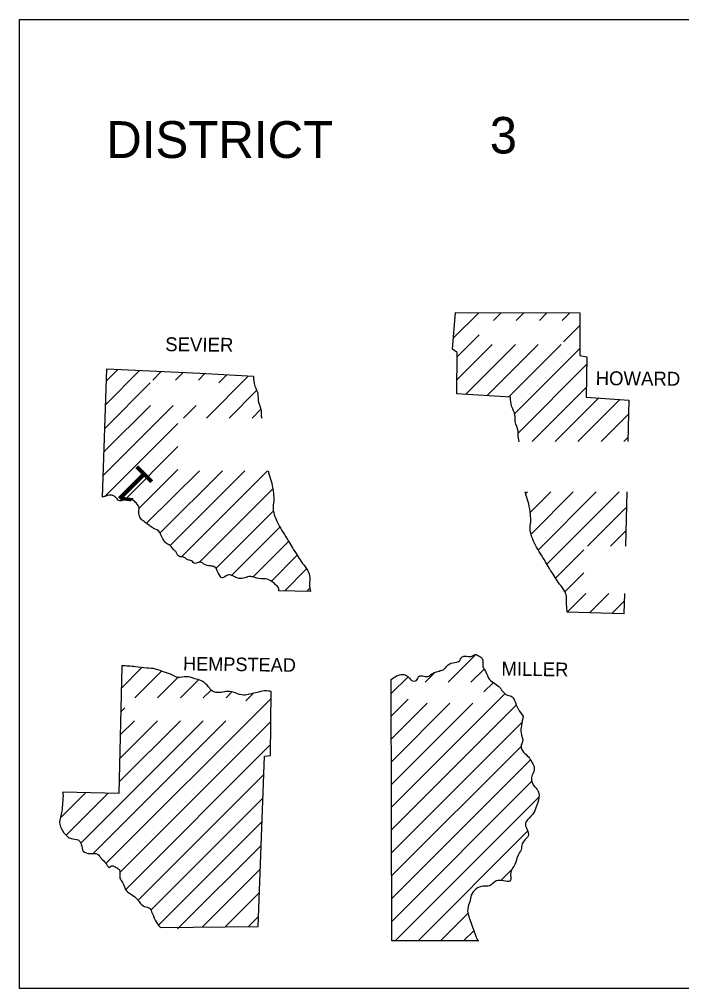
# Model space of a CAD drawing. Extents: x 23481 to 28196, y 1325020 to 1327623.
# Drawn here: x 27550.2 to 27755.3, y 1327036.8 to 1327336.8 of the extents above; entities that cross this region are included whole.
import ezdxf

# ---------------------------------------------------------------- set-up
doc = ezdxf.new("R2010")
doc.units = 0
doc.layers.add('S_ELECTRIC_UTILITIES_ANNOT', color=7, linetype='Continuous')

msp = doc.modelspace()

# ---------------------------------------------------------------- linework, layer by layer
at = {"layer": 'S_ELECTRIC_UTILITIES_ANNOT'}
msp.add_line((27719.9, 1327153.35), (27719.8, 1327155.05), dxfattribs=at)
msp.add_lwpolyline([(27550.24, 1327036.83), (27550.24, 1327336.83), (27950.24, 1327336.83), (27950.24, 1327036.83)], close=True, dxfattribs=at)
for points in [[(27685.7, 1327220.95), (27685.8, 1327233.75), (27684.4, 1327234.75), (27685.3, 1327246.15), (27723.8, 1327246.05)], [(27684.7, 1327238.25), (27692.5, 1327246.05)], [(27685.3, 1327245.95), (27685.4, 1327246.05)], [(27697.1, 1327243.65), (27699.5, 1327246.05)], [(27704.1, 1327243.65), (27706.5, 1327246.05)], [(27711.3, 1327243.65), (27713.6, 1327246.05)], [(27718.3, 1327243.65), (27720.7, 1327246.05)], [(27723.8, 1327246.05), (27723.8, 1327232.75), (27726, 1327232.35), (27725.8, 1327219.95), (27739, 1327218.95), (27738.7, 1327206.15)], [(27718.8, 1327237.05), (27723.8, 1327242.05)], [(27685.7, 1327232.25), (27692.6, 1327239.15)], [(27685.7, 1327225.25), (27696.7, 1327236.25)], [(27688.4, 1327220.75), (27703.9, 1327236.25)], [(27695, 1327220.35), (27710.9, 1327236.25)], [(27701.7, 1327219.95), (27718, 1327236.25)], [(27703.6, 1327214.75), (27723.8, 1327234.95)], [(27704.8, 1327208.85), (27725.9, 1327230.05)], [(27576, 1327188.95), (27577.3, 1327228.65)], [(27577, 1327217.65), (27587.4, 1327228.15)], [(27577.3, 1327228.65), (27606.1, 1327227.35)], [(27577.3, 1327225.05), (27580.7, 1327228.45)], [(27591.6, 1327225.15), (27594.2, 1327227.85)], [(27598.6, 1327225.15), (27601, 1327227.55)], [(27605.7, 1327225.15), (27607.7, 1327227.25)], [(27606.1, 1327227.35), (27622.7, 1327226.35)], [(27576.8, 1327210.35), (27590.7, 1327224.35)], [(27608.2, 1327213.45), (27621.1, 1327226.45)], [(27612, 1327224.35), (27614.4, 1327226.75)], [(27615.2, 1327213.45), (27623.6, 1327221.85)], [(27709.1, 1327206.15), (27725.8, 1327222.85)], [(27702.3, 1327219.95), (27685.7, 1327220.95)], [(27716.2, 1327206.15), (27729.7, 1327219.65)], [(27723.2, 1327206.15), (27736.2, 1327219.15)], [(27576.3, 1327195.75), (27597.9, 1327217.35)], [(27576.5, 1327203.05), (27590.8, 1327217.35)], [(27601.1, 1327213.45), (27605, 1327217.35)], [(27622.3, 1327213.45), (27625.1, 1327216.25)], [(27730.4, 1327206.15), (27738.9, 1327214.65)], [(27576.6, 1327189.05), (27599.3, 1327211.75)], [(27737.4, 1327206.15), (27738.7, 1327207.45)], [(27582.8, 1327188.05), (27599.3, 1327204.65)], [(27587.3, 1327185.55), (27599.3, 1327197.55)], [(27589.6, 1327180.85), (27606, 1327197.15)], [(27593.8, 1327177.95), (27613.1, 1327197.15)], [(27596.9, 1327173.95), (27620.1, 1327197.15)], [(27600.6, 1327170.55), (27627.1, 1327197.05)], [(27605.9, 1327168.75), (27628.7, 1327191.55)], [(27707.1, 1327190.05), (27707.6, 1327190.55)], [(27708.5, 1327184.35), (27714.8, 1327190.55)], [(27708.8, 1327177.55), (27721.8, 1327190.55)], [(27711, 1327172.65), (27728.9, 1327190.55)], [(27713.6, 1327168.25), (27736, 1327190.55)], [(27738.4, 1327190.55), (27738, 1327173.75)], [(27726.2, 1327173.75), (27738.1, 1327185.65)], [(27611.1, 1327166.85), (27628.8, 1327184.65)], [(27615.8, 1327164.55), (27630.9, 1327179.65)], [(27733.3, 1327173.75), (27738, 1327178.45)], [(27622.6, 1327164.25), (27633.6, 1327175.25)], [(27628.3, 1327162.95), (27636.3, 1327170.95)], [(27716.4, 1327163.95), (27725.1, 1327172.65)], [(27632.4, 1327159.95), (27639.2, 1327166.75)], [(27719.3, 1327159.75), (27725.1, 1327165.55)], [(27640.5, 1327159.75), (27630.6, 1327159.95)], [(27639.3, 1327159.85), (27640.3, 1327160.85)], [(27719.9, 1327153.35), (27725.7, 1327159.15)], [(27737.6, 1327159.15), (27737.4, 1327152.85), (27719.9, 1327153.35)], [(27726.8, 1327153.15), (27732.8, 1327159.15)], [(27733.8, 1327153.05), (27737.6, 1327156.85)], [(27683, 1327131.65), (27691.6, 1327140.25)], [(27582, 1327136.65), (27581, 1327097.25), (27563.7, 1327097.65)], [(27581.8, 1327129.75), (27588.1, 1327136.15)], [(27586, 1327126.85), (27594.1, 1327134.95)], [(27675.9, 1327131.65), (27678.8, 1327134.55)], [(27690.1, 1327131.65), (27694.2, 1327135.75)], [(27593, 1327126.85), (27599.3, 1327133.15)], [(27600.1, 1327126.85), (27605.6, 1327132.35)], [(27665.4, 1327128.15), (27670.6, 1327133.35)], [(27692.5, 1327051.65), (27665.6, 1327051.65), (27665.4, 1327132.55)], [(27694.1, 1327128.65), (27697.1, 1327131.55)], [(27607.2, 1327126.85), (27609.6, 1327129.25)], [(27614.3, 1327126.85), (27615.9, 1327128.55)], [(27620.4, 1327125.95), (27622.7, 1327128.25)], [(27624.2, 1327056.05), (27626.2, 1327108.75), (27628, 1327108.95), (27628.2, 1327128.85)], [(27665.5, 1327092.95), (27700.7, 1327128.15)], [(27577.1, 1327075.65), (27628.2, 1327126.65)], [(27665.4, 1327121.15), (27670.7, 1327126.45)], [(27665.5, 1327100.05), (27690.7, 1327125.15)], [(27665.5, 1327107.05), (27683.6, 1327125.15)], [(27665.5, 1327114.15), (27676.5, 1327125.15)], [(27581.6, 1327122.45), (27582.9, 1327123.75)], [(27665.5, 1327085.95), (27704.1, 1327124.55)], [(27569.3, 1327081.85), (27607.2, 1327119.75)], [(27573.2, 1327078.75), (27614.2, 1327119.75)], [(27581.1, 1327100.85), (27600.1, 1327119.75)], [(27581.3, 1327108.05), (27593, 1327119.75)], [(27581.4, 1327115.25), (27585.9, 1327119.75)], [(27581.4, 1327072.75), (27628.1, 1327119.55)], [(27665.5, 1327078.85), (27705.7, 1327119.05)], [(27583.3, 1327067.65), (27628, 1327112.35)], [(27665.6, 1327071.85), (27705.6, 1327111.75)], [(27665.6, 1327064.75), (27708.5, 1327107.65)], [(27587, 1327064.25), (27626, 1327103.25)], [(27665.6, 1327057.65), (27708.9, 1327101.05)], [(27563.2, 1327089.95), (27570.8, 1327097.55)], [(27564.7, 1327084.35), (27577.7, 1327097.35)], [(27591, 1327061.15), (27625.7, 1327095.85)], [(27666.6, 1327051.65), (27711.1, 1327096.05)], [(27593.3, 1327056.45), (27625.4, 1327088.55)], [(27673.7, 1327051.65), (27707.5, 1327085.45)], [(27599.2, 1327055.35), (27599.7, 1327055.85), (27625.1, 1327081.15)], [(27607, 1327055.95), (27624.8, 1327073.85)], [(27699.3, 1327070.25), (27702.9, 1327073.85)], [(27614.1, 1327056.05), (27624.6, 1327066.55)], [(27621.2, 1327056.05), (27624.3, 1327059.15)], [(27680.7, 1327051.65), (27689.1, 1327060.05)], [(27593.9, 1327055.75), (27624.2, 1327056.05)], [(27687.8, 1327051.65), (27691, 1327054.75)]]:
    msp.add_lwpolyline(points, dxfattribs=at)
for points in [[(27622.7, 1327226.35), (27623.2, 1327223.35), (27624.1, 1327220.75), (27624.2, 1327218.75), (27625.1, 1327215.75), (27625.1, 1327214.65), (27625.3, 1327213.45)], [(27705, 1327206.05), (27705, 1327206.15), (27704.7, 1327208.25), (27704.7, 1327209.35), (27703.8, 1327212.35), (27703.7, 1327214.35), (27702.8, 1327216.95), (27702.3, 1327219.95)], [(27627.3, 1327197.15), (27627.6, 1327195.85), (27628.4, 1327193.25), (27628.9, 1327190.05), (27629, 1327187.65), (27628.8, 1327185.45), (27629.4, 1327182.95), (27630.5, 1327180.45), (27631.9, 1327178.05), (27633.6, 1327175.35), (27634.8, 1327173.25), (27636.3, 1327170.95), (27637.5, 1327169.05), (27639.3, 1327166.65), (27640.1, 1327164.65), (27640.1, 1327161.85), (27640.4, 1327159.75)], [(27630.6, 1327159.95), (27630.6, 1327160.55), (27629.6, 1327161.85), (27628.1, 1327163.05), (27626.5, 1327163.65), (27625, 1327163.65), (27622.6, 1327164.25), (27621.3, 1327164.35), (27619.6, 1327163.85), (27617.7, 1327163.95), (27614.7, 1327164.85), (27613.1, 1327163.95), (27611.8, 1327165.55), (27610.5, 1327167.45), (27609.4, 1327167.65), (27607.4, 1327168.25), (27605.9, 1327168.85), (27604.7, 1327168.45), (27603.5, 1327169.25), (27602.4, 1327169.55), (27600.9, 1327170.45), (27599.8, 1327170.55), (27598.8, 1327171.95), (27598.2, 1327172.55), (27596.9, 1327173.95), (27595.7, 1327174.75), (27594.7, 1327176.05), (27593.9, 1327177.65), (27593.7, 1327178.05), (27591.7, 1327179.35), (27590.5, 1327180.15), (27589.2, 1327181.15), (27588, 1327182.15), (27587.3, 1327183.45), (27587.2, 1327184.05), (27587.3, 1327185.55), (27586.4, 1327187.15), (27585.3, 1327188.05), (27583.8, 1327188.15), (27582.2, 1327187.95), (27581.3, 1327187.85), (27579.8, 1327189.15), (27576, 1327188.95)], [(27719.8, 1327155.05), (27719.7, 1327155.45), (27719.7, 1327158.25), (27718.9, 1327160.25), (27717.1, 1327162.65), (27715.9, 1327164.55), (27714.4, 1327166.85), (27713.2, 1327168.95), (27711.5, 1327171.65), (27710.1, 1327174.05), (27709, 1327176.55), (27708.4, 1327179.05), (27708.6, 1327181.25), (27708.5, 1327183.65), (27708, 1327186.85), (27707.2, 1327189.45), (27706.9, 1327190.55)], [(27665.4, 1327132.55), (27668.9, 1327134.05), (27670.4, 1327133.55), (27671.7, 1327132.25), (27673.2, 1327132.25), (27674, 1327133.45), (27675.5, 1327133.55), (27676.7, 1327133.45), (27678, 1327134.25), (27679.1, 1327134.75), (27680.6, 1327135.25), (27681.7, 1327135.65), (27682.7, 1327136.75), (27684.5, 1327137.65), (27686.6, 1327138.35), (27687.2, 1327139.35), (27688.2, 1327139.75), (27690.2, 1327139.65), (27691.5, 1327140.25), (27692.6, 1327139.75), (27693.6, 1327139.05), (27693.8, 1327136.45), (27694.6, 1327135.05), (27695.8, 1327132.55), (27697.5, 1327131.25), (27699.1, 1327129.95), (27699.7, 1327129.15), (27701.4, 1327127.65), (27702.9, 1327127.15), (27703.6, 1327126.05), (27704.7, 1327123.45), (27706.3, 1327121.15)], [(27628.2, 1327128.75), (27627.4, 1327128.95), (27624.9, 1327128.75), (27622.9, 1327128.25), (27621.2, 1327127.85), (27619.1, 1327127.75), (27616.5, 1327128.55), (27614.2, 1327128.75), (27612.3, 1327128.45), (27610, 1327128.95), (27608.8, 1327130.25), (27606.9, 1327131.95), (27604.3, 1327132.85), (27602, 1327133.35), (27599.3, 1327133.15), (27597.7, 1327133.85), (27595.2, 1327134.75), (27592.4, 1327135.75), (27589.7, 1327136.05), (27586.2, 1327136.45), (27581.9, 1327136.75)], [(27706.3, 1327121.15), (27705.7, 1327118.25), (27705.6, 1327115.95), (27706.1, 1327113.25), (27705.6, 1327111.95), (27706.4, 1327110.05), (27707.9, 1327108.55), (27709, 1327106.95), (27709.7, 1327104.65), (27708.8, 1327102.05), (27709.8, 1327099.35), (27710.7, 1327098.35), (27711.2, 1327096.75), (27710.5, 1327093.65), (27709.6, 1327091.35), (27707.6, 1327089.05), (27707, 1327087.95), (27707.3, 1327086.45), (27707.8, 1327084.05), (27707.3, 1327083.35), (27706, 1327081.65), (27705.6, 1327079.75), (27704.7, 1327078.15), (27703.7, 1327075.25), (27702.4, 1327072.85), (27702.2, 1327070.15), (27700.2, 1327070.15), (27697.9, 1327070.15), (27695.8, 1327068.65), (27693.9, 1327068.55), (27691.6, 1327067.65), (27690.2, 1327065.75), (27689.7, 1327063.65), (27689.1, 1327061.65), (27689.7, 1327058.25), (27690.6, 1327055.85), (27691.3, 1327053.95), (27692.2, 1327051.55)], [(27563.6, 1327097.75), (27563.7, 1327097.25), (27563.6, 1327094.35), (27563.4, 1327091.75), (27562.7, 1327088.15), (27563.2, 1327086.45), (27565.1, 1327083.95), (27566.3, 1327083.25), (27568.4, 1327082.85), (27569.4, 1327081.45), (27570, 1327079.35), (27572.1, 1327078.65), (27574.4, 1327078.45), (27575.5, 1327077.25), (27577, 1327075.65), (27577.9, 1327074.25)], [(27577.9, 1327074.25), (27579.1, 1327074.85), (27580.2, 1327074.35), (27581.2, 1327073.65), (27581.4, 1327071.05), (27582.2, 1327069.65), (27583.4, 1327067.15), (27585.1, 1327065.85), (27586.7, 1327064.55), (27587.3, 1327063.75), (27589, 1327062.25), (27590.5, 1327061.75), (27591.2, 1327060.65), (27592.3, 1327058.05), (27593.9, 1327055.75)]]:
    msp.add_spline(points, degree=3, dxfattribs=at)

# ---------------------------------------------------------------- texts
for s, height, p in [('DISTRICT', 11.4, (27577.14, 1327293.93)), ('3', 11.3, (27695.94, 1327295.33))]:
    msp.add_text(s, height=height, dxfattribs=at).set_placement(p)
for s, height, rotation, p in [('SEVIER', 4.301, 359.4271, (27595.4, 1327234.15)), ('HOWARD', 4.301, 359.5145, (27728.7, 1327223.65)), ('1', 11.4, 135, (27592.5, 1327193.35)), ('HEMPSTEAD', 4.199, 359.1885, (27600.9, 1327135.35)), ('MILLER', 4.3, 359.1319, (27699.5, 1327133.75))]:
    msp.add_text(s, height=height, rotation=rotation, dxfattribs=at).set_placement(p)

doc.saveas('drawing.dxf')
